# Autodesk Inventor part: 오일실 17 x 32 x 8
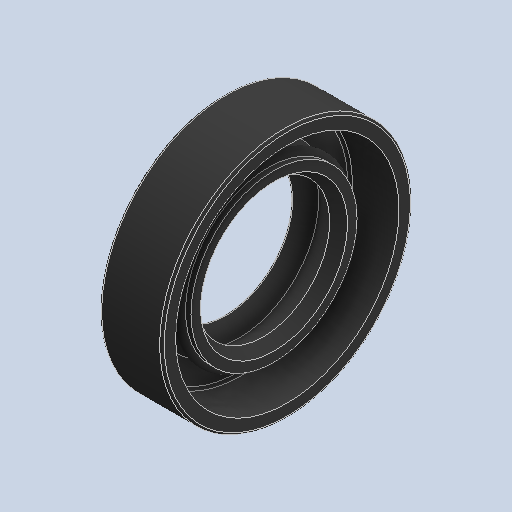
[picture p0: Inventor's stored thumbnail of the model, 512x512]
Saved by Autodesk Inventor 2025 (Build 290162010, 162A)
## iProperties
Created: 2024-07
Part Number: 오일실 17 x 32 x 8
Material: 고무
Description: 오일-실
Document SubType Name: Modeling
Designer: 계정
Density: 0.93 g/cm^3
Appearance: 기본값
Author: jhkim
Sending System: Autodesk Inventor 2025
Preprocessor: ST-DEVELOPER v20
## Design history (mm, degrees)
feature "Solid1"
node "솔리드1"
